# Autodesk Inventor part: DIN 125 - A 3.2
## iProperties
Created: 2004-03
Part Number: DIN 125 - A 3.2
Material: Standard
Catalog Web Link: file:///C:/Programme/Autodesk/Inventor 5.3/Content/Din/index.htm?doNavigateId=CB387C1A-C465-11D4-A9F1-0080AD303E0A|722B110FB16B11D4BA6900C04F798F98|true
Description: Scheibe
Document SubType Name: Standard Catalog Part
Standard: DIN 125 - A 3.2
Designer: UR
Control State: 0
Master: False
Checked Out: False
Shininess: 20.0
Angle Display Precision: 2
Document Length Units: 11269
Document Angle Units: 11279
Document Time Units: 11290
Document Mass Units: 11283
Document Length Units Precision: 3
Document Angle Units Precision: 2
Compacted: True
KLASSIFIKATION: 31161807 un/spsc
HERSTELLER: DIN Normsystem
Density: 0.0
Volumn: 0.0
Area: 0.0
PropertySet Name: Model Information
Author: UR
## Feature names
1. Basis1
